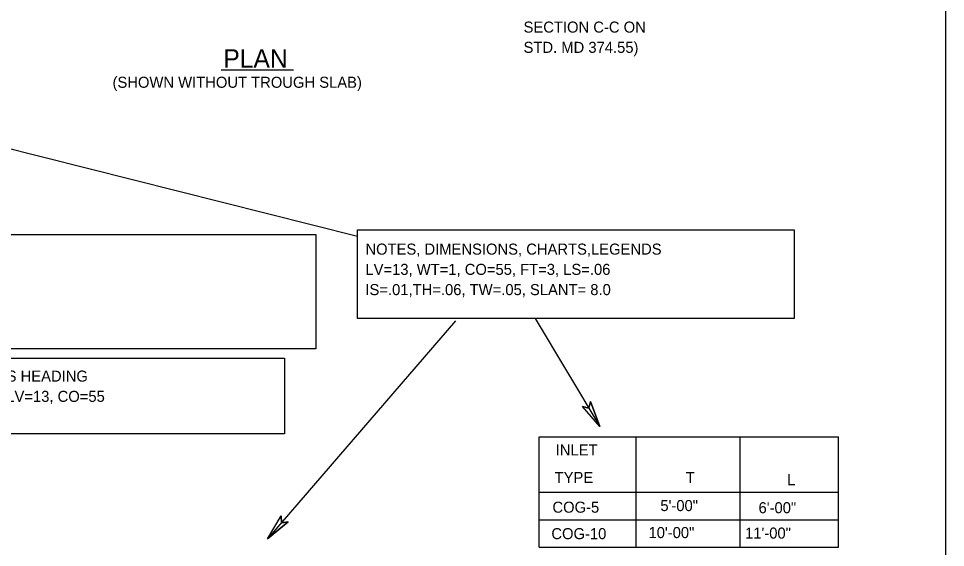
# Model space of a CAD drawing. Extents: x 0 to 1549163, y -476626 to 622136.
# Drawn here: x 2.73 to 7.77, y 9.26 to 12.13 of the extents above; entities that cross this region are included whole.
import ezdxf

# ---------------------------------------------------------------- set-up
doc = ezdxf.new("R2010")
doc.units = 0
for name, color, linetype in [('DETL-DIMS', 7, 'Continuous'), ('DETL-LINE', 7, 'Continuous'), ('DETL-NOTE', 7, 'Continuous'), ('DETL-TITL', 7, 'Continuous'), ('TTLB-TEXT', 7, 'Continuous')]:
    doc.layers.add(name, color=color, linetype=linetype)

msp = doc.modelspace()

# ---------------------------------------------------------------- linework, layer by layer
at = {"layer": 'DETL-DIMS'}
for p, q in [((4.5743, 10.9505), (1.9064, 11.6206)), ((5.1052, 10.4925), (4.0848, 9.3079)), ((5.5392, 10.5042), (5.8911, 9.9178)), ((5.8911, 9.9178), (5.7959, 10.0274)), ((5.8314, 10.0173), (5.7959, 10.0274)), ((5.8391, 10.0534), (5.8314, 10.0173)), ((5.8911, 9.9178), (5.8391, 10.0534)), ((4.0848, 9.3079), (4.159, 9.4327)), ((4.1605, 9.3958), (4.159, 9.4327)), ((4.0848, 9.3079), (4.1972, 9.3998)), ((4.1972, 9.3998), (4.1605, 9.3958))]:
    msp.add_line(p, q, dxfattribs=at)
for points in [[(5.8391, 10.0534), (5.8911, 9.9178), (5.7959, 10.0274), (5.8314, 10.0173)], [(4.1972, 9.3998), (4.0848, 9.3079), (4.159, 9.4327), (4.1605, 9.3958)]]:
    msp.add_lwpolyline(points, close=True, dxfattribs=at)
at = {"layer": 'DETL-LINE'}
msp.add_lwpolyline([(1.8813, 10.2894), (4.1762, 10.2894), (4.1762, 9.8785), (1.8813, 9.8785)], close=True, dxfattribs=at)
at = {"layer": 'DETL-NOTE'}
for p, q in [((5.5606, 9.8621), (7.1873, 9.8621)), ((5.5606, 9.2621), (5.5606, 9.8621)), ((6.0877, 9.2621), (6.0877, 9.8621)), ((6.6536, 9.2621), (6.6536, 9.8621)), ((7.1873, 9.2621), (7.1873, 9.8621)), ((5.5606, 9.5621), (7.1873, 9.5621)), ((5.5606, 9.4121), (7.1873, 9.4121)), ((5.5606, 9.2621), (7.1873, 9.2621))]:
    msp.add_line(p, q, dxfattribs=at)
for points in [[(4.5743, 10.9863), (6.9467, 10.9863), (6.9467, 10.5047), (4.5743, 10.5047)], [(0.5997, 10.961), (4.3466, 10.961), (4.3466, 10.3397), (0.5997, 10.3397)]]:
    msp.add_lwpolyline(points, close=True, dxfattribs=at)
at = {"layer": 'DETL-TITL'}
msp.add_line((3.8321, 11.855), (4.2261, 11.855), dxfattribs=at)
at = {"layer": 'TTLB-TEXT'}
msp.add_lwpolyline([(0.3943, 16.2906), (7.7685, 16.2906), (7.7685, 5.9375), (0.3943, 5.9375)], close=True, dxfattribs=at)

# ---------------------------------------------------------------- texts
at = {"layer": 'DETL-LINE'}
for s, p in [('LINE UNDER NOTES HEADING ', (1.9358, 10.1619)), ('AA=0,L=0.4, WT=4, LV=13, CO=55', (1.9358, 10.0519))]:
    msp.add_text(s, height=0.06, dxfattribs=at).set_placement(p)
at = {"layer": 'DETL-NOTE'}
for s, p in [('SECTION C-C ON', (5.4759, 12.0576)), ('STD. MD 374.55)', (5.4759, 11.9476)), ('(SHOWN WITHOUT TROUGH SLAB)', (3.2423, 11.7579)), ('NOTES, DIMENSIONS, CHARTS,LEGENDS', (4.6165, 10.8517)), ('LV=13, WT=1, CO=55, FT=3, LS=.06', (4.6165, 10.7417)), ('IS=.01,TH=.06, TW=.05, SLANT= 8.0', (4.6165, 10.6317)), ('INLET', (5.6504, 9.7607)), ('TYPE', (5.6446, 9.6111)), ('T', (6.3571, 9.6111)), ('L', (6.9084, 9.5994)), ('COG-5', (5.6328, 9.4499)), ('5\'-00"', (6.2193, 9.4587)), ('6\'-00"', (6.7529, 9.4471)), ('10\'-00"', (6.1548, 9.3121)), ('11\'-00"', (6.6796, 9.3092)), ('COG-10', (5.627, 9.3062))]:
    msp.add_text(s, height=0.06, dxfattribs=at).set_placement(p)
at = {"layer": 'DETL-TITL'}
msp.add_text('PLAN', height=0.1, dxfattribs=at).set_placement((3.8446, 11.8675))

doc.saveas('drawing.dxf')
